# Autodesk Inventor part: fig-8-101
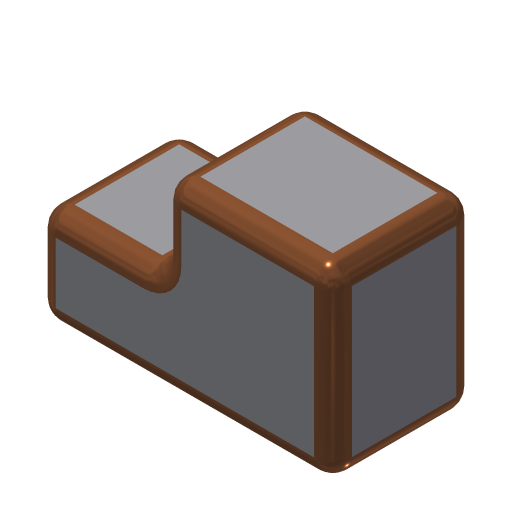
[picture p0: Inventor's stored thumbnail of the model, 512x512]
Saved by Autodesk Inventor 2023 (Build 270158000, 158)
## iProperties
Part Number: fig-8-101
Document SubType Name: Modeling
Created: 2002-12
Designer: deepak
Density: 1 g/cm^3
Material: Generic
Appearance: Default
Control State: 0
Master: False
Checked Out: False
Shininess: 64.0
Length Units: 11269
Angle Units: 11279
Time Units: 11290
Mass Units: 11283
Length Display Precision: 3
Angle Display Precision: 2
Compacted: True
Density: 0.0
Volumn: 0.0
Area: 0.0
PropertySet Name: Model Information
Author: deepak
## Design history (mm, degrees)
sketch "Sketch1"
  geometry: L1 (-26.972, 23.346)-(8.906, 23.346); L2 (8.906, 23.346)-(8.906, 5.025); L3 (8.906, -15.84)-(-26.972, -15.84); L4 (-26.972, -15.84)-(-26.972, 23.346); L5 (8.906, -15.84)-(35.369, -15.84); L6 (35.369, -15.84)-(35.369, 5.025); L7 (35.369, 5.025)-(8.906, 5.025)
  constraints: 14 end point, 3 parallel, 2 horizontal, 2 perpendicular
extrude "Extrusion1" new body sketch "Sketch1" stored distance "d0" = 30; taper "d1" = 0 deg
fillet "Fillet1" dims "d2" = 4, "d3" = 4
body "Solid1"
